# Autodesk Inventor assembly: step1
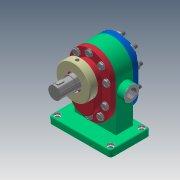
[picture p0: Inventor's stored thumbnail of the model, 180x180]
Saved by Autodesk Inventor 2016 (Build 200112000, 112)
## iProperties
Created: 2013-11
Part Number: step1
Document SubType Name: Assembly
Designer: normanpa
Author: normanpa
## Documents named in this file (11)
- C:\_P4_Inv_R20QA\inventor\streams\Shelby\R20QA\PSS\InteractiveTutorial\Drawing_3\TutorialModelPath\step1.iam
- C:\_P4_Inv_R20QA\inventor\streams\Shelby\R20QA\PSS\InteractiveTutorial\Drawing_3\TutorialModelPath\Pump_Components\Pump Base.ipt
- C:\_P4_Inv_R20QA\inventor\streams\Shelby\R20QA\PSS\InteractiveTutorial\Drawing_3\TutorialModelPath\Pump_Components\Pump_Back_Cover.ipt
- C:\_P4_Inv_R20QA\inventor\streams\Shelby\R20QA\PSS\InteractiveTutorial\Drawing_3\TutorialModelPath\Pump_Components\Pump_Front_Cover.ipt
- C:\_P4_Inv_R20QA\inventor\streams\Shelby\R20QA\PSS\InteractiveTutorial\Drawing_3\TutorialModelPath\Pump_Components\Lock_Ring.ipt
- C:\_P4_Inv_R20QA\inventor\streams\Shelby\R20QA\PSS\InteractiveTutorial\Drawing_3\TutorialModelPath\Pump_Components\Drive_Shaft.ipt
- C:\_P4_Inv_R20QA\inventor\streams\Shelby\R20QA\PSS\InteractiveTutorial\Drawing_3\TutorialModelPath\Pump_Components\Driven_Shaft_Gear.ipt
- C:\_P4_Inv_R20QA\inventor\streams\Shelby\R20QA\PSS\InteractiveTutorial\Drawing_3\TutorialModelPath\Pump_Components\ISO 2491 - A  10 x 6 x 22.ipt
- C:\_P4_Inv_R20QA\inventor\streams\Shelby\R20QA\PSS\InteractiveTutorial\Drawing_3\TutorialModelPath\Pump_Components\Packing_2.ipt
- C:\_P4_Inv_R20QA\inventor\streams\Shelby\R20QA\PSS\InteractiveTutorial\Drawing_3\TutorialModelPath\Pump_Components\Packing_1.ipt
- C:\_P4_Inv_R20QA\inventor\streams\Shelby\R20QA\PSS\InteractiveTutorial\Drawing_3\TutorialModelPath\Pump_Components\BoltedConnection.iam
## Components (22 placed, 10 different names)
1. Pump Base:1 — Rigid:1, Rigid:2, Angle:1
2. Pump_Back_Cover:1 — Rigid:2, Rotational:1, Rotational:2
3. Pump_Front_Cover:1 — Rigid:1, Rigid:3, Rigid:5, Rigid:6
4. Lock_Ring:1 — Rigid:3
5. Drive_Shaft:1 — Rotational:1, Rigid:4, Rotational:3, Angle:1
6. Driven_Shaft — Rotational:2
7. ISO 2491 A A  10 x 6 x 22:1 — Rigid:4
8. Packing_2:1 — Rotational:3, Rotational:4
9. Packing_1:1 — Rotational:4, Rotational:5
10. Packing_1:2 — Rotational:5, Rotational:6
11. Packing_1:3 — Rotational:6, Rotational:7
12. Packing_2:2 — Rotational:7
13. BoltedConnection:1 [sub-assembly] — Rigid:5
14. BoltedConnection:2 [sub-assembly]
15. BoltedConnection:3 [sub-assembly]
16. BoltedConnection:4 [sub-assembly]
17. BoltedConnection:5 [sub-assembly]
18. BoltedConnection:6 [sub-assembly] — Rigid:6
19. BoltedConnection:7 [sub-assembly]
20. BoltedConnection:8 [sub-assembly]
21. BoltedConnection:9 [sub-assembly]
22. BoltedConnection:10 [sub-assembly]
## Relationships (14: RevoluteJoint 7, WeldJoint 6, Angle 1)
- Rigid:1 [WeldJoint]: Pump Base:1 ↔ Pump_Front_Cover:1
- Rigid:2 [WeldJoint]: Pump Base:1 ↔ Pump_Back_Cover:1
- Rigid:3 [WeldJoint]: Pump_Front_Cover:1 ↔ Lock_Ring:1
- Rotational:1 [RevoluteJoint]: Pump_Back_Cover:1 ↔ Drive_Shaft:1
- Rotational:2 [RevoluteJoint]: Pump_Back_Cover:1 ↔ Driven_Shaft
- Rigid:4 [WeldJoint]: Drive_Shaft:1 ↔ ISO 2491 A A  10 x 6 x 22:1
- Rotational:3 [RevoluteJoint]: Drive_Shaft:1 ↔ Packing_2:1
- Rotational:4 [RevoluteJoint]: Packing_2:1 ↔ Packing_1:1
- Rotational:5 [RevoluteJoint]: Packing_1:1 ↔ Packing_1:2
- Rotational:6 [RevoluteJoint]: Packing_1:2 ↔ Packing_1:3
- Rotational:7 [RevoluteJoint]: Packing_1:3 ↔ Packing_2:2
- Angle:1: Pump Base:1 ↔ Drive_Shaft:1
- Rigid:5 [WeldJoint]: Pump_Front_Cover:1 ↔ BoltedConnection:1
- Rigid:6 [WeldJoint]: Pump_Front_Cover:1 ↔ BoltedConnection:6
